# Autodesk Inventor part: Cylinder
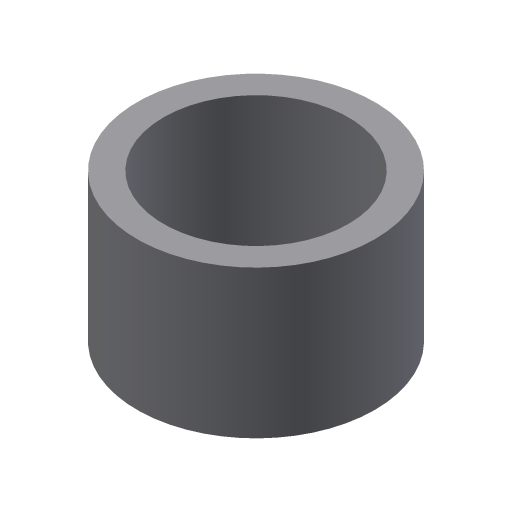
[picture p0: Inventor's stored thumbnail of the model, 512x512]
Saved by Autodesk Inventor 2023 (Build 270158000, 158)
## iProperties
Created: 2010-05
Part Number: Cylinder
Document SubType Name: Modeling
Designer: CADSoft
Density: 1 g/cm^3
Material: Generic
Appearance: Default
Author: CADSoft
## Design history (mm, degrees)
sketch "Sketch1"
  geometry: C1 r 87.5 at (0, 0); C2 r 112.5 at (0, 0); 1 further point
  constraints: 2 centre point, 2 coincident
  dimensions: "d0" = 175 diameter of C1; "d1" = 225 diameter of C2
extrude "Extrusion1" new body sketch "Sketch1" distance "d2" = 140; taper "d3" = 0 deg
body "Solid1"
